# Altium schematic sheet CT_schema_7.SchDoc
size 278 x 170 mm
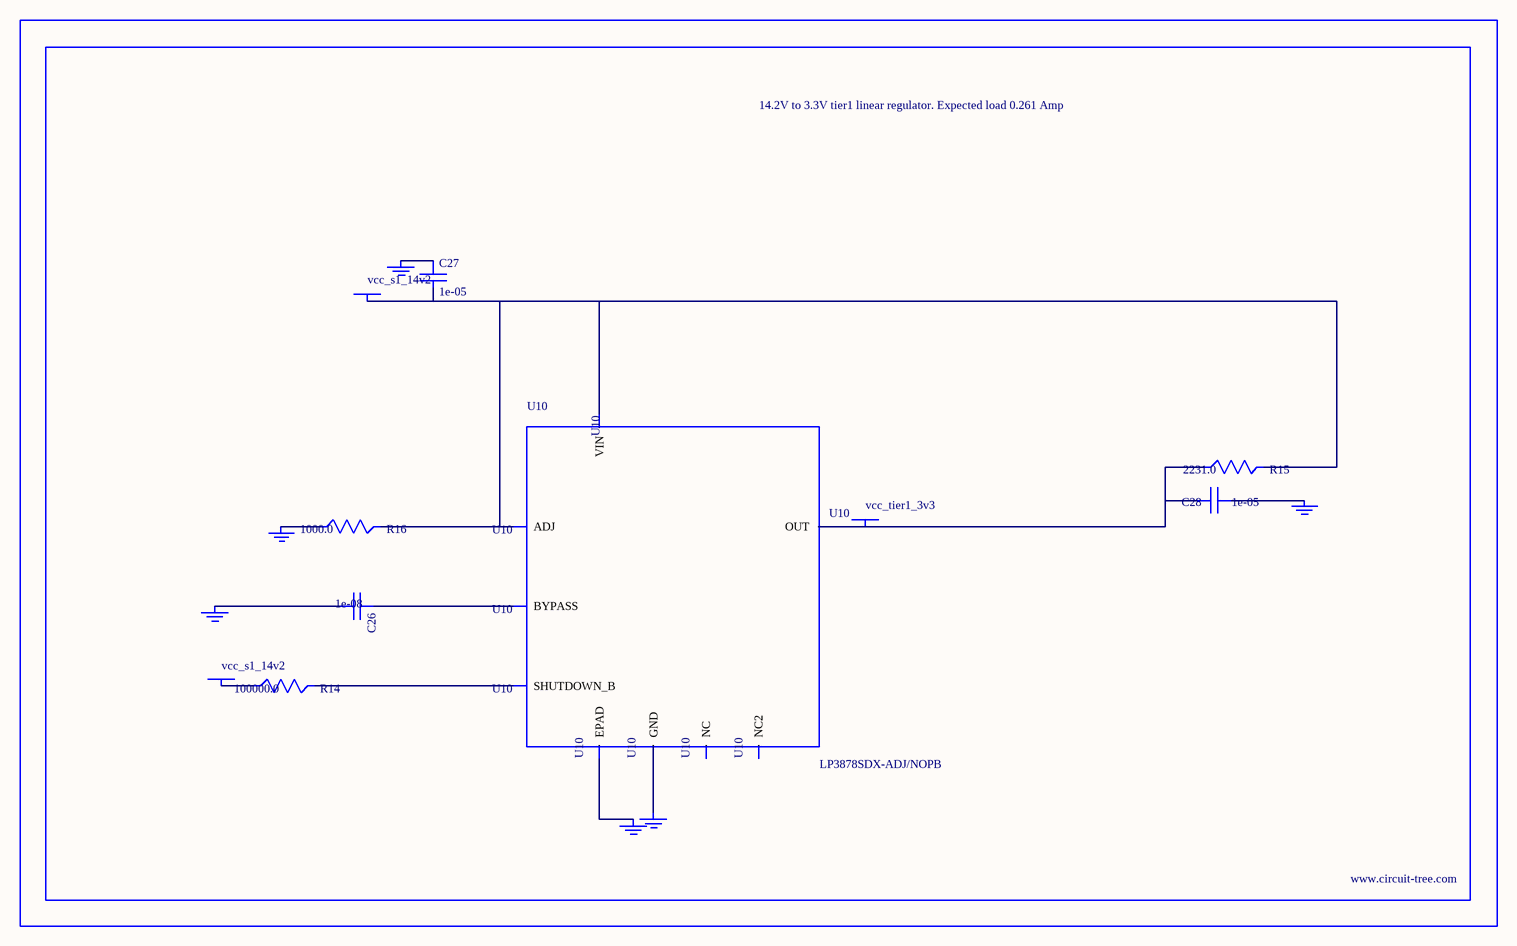
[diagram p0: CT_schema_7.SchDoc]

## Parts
BORDER6  (no value)
C26  1e-08  [C0402]
C27  1e-05  [C1210]
C28  1e-05  [C1210]
GND_INSTANCE_6_0  (no value)
GND_INSTANCE_6_1  (no value)
GND_INSTANCE_6_2  (no value)
GND_INSTANCE_6_3  (no value)
GND_INSTANCE_6_4  (no value)
GND_INSTANCE_6_5  (no value)
POWER_INSTANCE_6_0  vcc_s1_14v2
POWER_INSTANCE_6_1  vcc_s1_14v2
POWER_INSTANCE_6_2  vcc_tier1_3v3
R14  100000.0  [R0603]
R15  2231.0  [R0603]
R16  1000.0  [R0603]
U10  LP3878SDX-ADJ/NOPB  [WSON-8]

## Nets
NetC26_1: C26.1 U10.1(BYPASS)
NetC26_2: C26.2 GND_INSTANCE_6_0.0(GND)
NetC27_1: C27.1 GND_INSTANCE_6_1.0(GND)
NetC27_2: C27.2 POWER_INSTANCE_6_0.0(PWR) R15.2 R16.2 U10.4(VIN) U10.6(ADJ)
NetC28_1: C28.1 GND_INSTANCE_6_2.0(GND)
NetC28_2: C28.2 POWER_INSTANCE_6_2.0(PWR) R15.1 U10.5(OUT)
NetGND_INSTANCE_6_3_0: GND_INSTANCE_6_3.0(GND) R16.1
NetGND_INSTANCE_6_4_0: GND_INSTANCE_6_4.0(GND) U10.PAD(EPAD)
NetGND_INSTANCE_6_5_0: GND_INSTANCE_6_5.0(GND) U10.3(GND)
NetPOWER_INSTANCE_6_1_0: POWER_INSTANCE_6_1.0(PWR) R14.1
NetR14_2: R14.2 U10.8(SHUTDOWN_B)

Not connected (* = marked no-connect by the designer): U10 2(NC) 7(NC2)

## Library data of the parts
BORDER6 = BORDER_PAGE6
C26 = C0402C103K3RAC
C27 = C1210C106K5PACTU
C28 = GRM32DR61E106MA12L
GND_INSTANCE_6_0-GND_INSTANCE_6_5 = GND
POWER_INSTANCE_6_0-POWER_INSTANCE_6_2 = PWR
R14 = RC0603JR-07100KL
R15 = R15
R16 = RC0603JR-071KL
